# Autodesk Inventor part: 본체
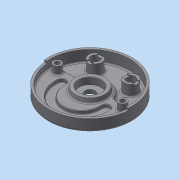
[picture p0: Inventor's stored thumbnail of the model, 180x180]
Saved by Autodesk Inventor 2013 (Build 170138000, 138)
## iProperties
Created: 2015-04
Part Number: 본체
Material: 일반
Document SubType Name: Modeling
Designer: Administrator
Density: 1 g/cm^3
Author: Administrator
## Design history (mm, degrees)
sketch "스케치1"
  geometry: C1 r 95 at (0, 0); 1 further point
  constraints: 1 centre point, 1 coincident
  dimensions: "d0" = 190 diameter of C1
extrude "돌출1" new body sketch "스케치1" distance "d1" = 32; taper "d2" = 0 deg
sketch "스케치2"
  geometry: L1 (-89.196, 12)-(-40.249, 12); L2 (40.249, 12)-(89.196, 12); C1 r 95 at (0, 0) reference; A1 r 90 centre (0, 0) between (89.196, 12) and (-89.196, 12); A2 r 42 centre (0, 0) between (40.249, 12) and (-40.249, 12)
  constraints: 4 end point, 4 point on circle, 2 centre point, 2 coincident, 2 horizontal
  dimensions: "d3" = 180 diameter of A1; "d4" = 84 diameter of A2; "d6" = 12 vertical distance of C1.centre L1.end; "d7" = 12 vertical distance of L2.end C1.centre
extrude "돌출2" cut sketch "스케치2" distance "d8" = 25; taper "d9" = 0 deg
fillet "모깎기1" dims "d10" = 10
sketch "스케치3"
  geometry: L1 (-47.117, 12)-(-76.916, 12) reference; L2 (76.916, 12)-(47.117, 12) reference; C1 r 95 at (0, 0) reference; C2 r 90 at (0, 0); A1 r 10 centre (-76.916, 22) between (-86.53, 24.75) and (-76.916, 12) reference; A2 r 90 centre (0, 0) between (86.53, 24.75) and (-86.53, 24.75) reference; A3 r 10 centre (76.916, 22) between (76.916, 12) and (86.53, 24.75) reference; A4 r 10 centre (47.117, 22) between (38.056, 17.769) and (47.117, 12) reference; A5 r 42 centre (0, 0) between (38.056, 17.769) and (-38.056, 17.769) reference; A6 r 10 centre (-47.117, 22) between (-47.117, 12) and (-38.056, 17.769) reference
  constraints: 1 centre point, 1 coincident
  dimensions: "d11" = 180 diameter of C2
extrude "돌출3" cut sketch "스케치3" distance "d12" = 18; taper "d13" = 0 deg
sketch "스케치6"
  geometry: C1 r 35 at (0, 0); A1 r 42 centre (0, 0) between (38.056, 17.769) and (-38.056, 17.769) reference
  constraints: 1 centre point, 1 coincident
  dimensions: "d34" = 70 diameter of C1
extrude "돌출4" join sketch "스케치6" distance "d35" = 10; taper "d36" = -10 deg
sketch "스케치7"
  geometry: C1 r 33.237 at (0, 0) reference; C2 r 25 at (0, 0)
  constraints: 1 centre point, 1 coincident
  dimensions: "d37" = 50 diameter of C2
extrude "돌출5" cut sketch "스케치7" distance "d38" = 15; taper "d39" = 0 deg
sketch "스케치8"
  geometry: C1 r 25 at (0, 0) reference; C2 r 11.5 at (0, 0)
  constraints: 1 centre point, 1 coincident
  dimensions: "d40" = 23 diameter of C2
extrude "돌출6" cut sketch "스케치8" stored distance "d41" = 15; taper "d42" = 0 deg
sketch "스케치9"
  geometry: C1 r 15 at (-40, 52); C2 r 15 at (40, 52); A1 r 90 centre (0, 0) between (86.53, 24.75) and (-86.53, 24.75) reference
  constraints: 2 centre point, 1 horizontal alignment
  dimensions: "d43" = 30 diameter of C1; "d44" = 30 diameter of C2; "d45" = 80 distance of C2.centre C1.centre; "d46" = 40 horizontal distance of C1.centre A1.centre; "d47" = 52 vertical distance of A1.centre C2.centre
extrude "돌출7" join sketch "스케치9" distance "d48" = 25; taper "d49" = 0 deg
sketch "스케치10"
  geometry: C1 r 15 at (0, 0) reference; C2 r 15 at (80, 0) reference; C3 r 10 at (0, 0); C4 r 10 at (80, 0); 1 further point
  constraints: 2 centre point, 2 coincident
  dimensions: "d50" = 20 diameter of C3; "d51" = 20 diameter of C4
extrude "돌출8" cut sketch "스케치10" stored distance "d52" = 25; taper "d53" = 0 deg
sketch "스케치11"
  geometry: C1 r 35 at (0, 0) reference; C2 r 9 at (-74, 0); C3 r 9 at (74, 0)
  constraints: 2 centre point, 2 horizontal alignment
  dimensions: "d54" = 18 diameter of C2; "d55" = 18 diameter of C3; "d56" = 148 distance of C3.centre C2.centre; "d57" = 74 distance of C2.centre C1.centre
extrude "돌출9" join sketch "스케치11" distance "d58" = 18; taper "d59" = 0 deg
sketch "스케치12"
  geometry: C1 r 9 at (-74, 0) reference; C2 r 10 at (40, 52) reference; C3 r 10 at (-40, 52) reference; C4 r 11.5 at (0, 0) reference; C5 r 95 at (0, 0) reference; C6 r 9 at (74, 0) reference; 2 further points
  constraints: 2 coincident
hole "구멍1" sketch "스케치12" at (-74, 0), (74, 0) diameter "d60" = 11; stored, may be unused: countersink angle "d64" = 90 deg, drill point angle "d66" = 0 deg; dims "d61" = 6, "d62" = 18, "d63" = 11, "d65" = 8
sketch "스케치13"
  geometry: L1 (-76.916, 12)-(-47.117, 12) reference; L2 (-59, -19)-(-41, -19); L3 (41, -19)-(59, -19); L4 (41, -19)-(41, -14); L5 (59, -19)-(59, -14); L6 (41, -14)-(59, -14); L7 (-59, -19)-(-59, -14); L8 (-41, -19)-(-41, -14); L9 (-41, -14)-(-59, -14); C1 r 35 at (0, 0) reference; A1 r 59 centre (0, -19) between (-59, -19) and (59, -19); A2 r 41 centre (0, -19) between (-41, -19) and (41, -19); A3 r 9 centre (50, -14) between (59, -14) and (41, -14); A4 r 9 centre (-50, -14) between (-41, -14) and (-59, -14)
  constraints: 16 end point, 8 point on circle, 4 centre point, 4 tangent, 2 midpoint, 2 parallel, 1 coincident, 1 collinear, 1 perpendicular, 1 vertical alignment
  dimensions: "d70" = 82 diameter of A2; "d72" = 19 distance of A1.centre C1.centre; "d75" = 5 distance of L4.end L3.start; "d76" = 5 distance of L5.end L3.end; "d79" = 59 radius of A1; "d80" = 5 distance of L7.end L2.start; "d81" = 5 distance of L8.end L2.end
extrude "돌출10" cut sketch "스케치13" distance "d83" = 7; taper "d84" = 0 deg
sketch "스케치16"
  geometry: L1 (0, 0)-(-112.328, 0); L2 (-89.658, -7.844)-(-94.638, -8.28); L3 (0, 0)-(105.461, 0); L4 (89.658, -7.844)-(94.638, -8.28); A1 r 95 centre (0, 0) between (-94.638, -8.28) and (94.638, -8.28) reference; A2 r 90 centre (0, 0) between (-89.658, -7.844) and (89.658, -7.844) reference
  constraints: 8 end point, 4 point on circle, 1 collinear, 1 horizontal
  dimensions: "d90" = 5 deg angle of L2 L1; "d91" = 5 deg angle of L4 L3; "d92" = 4.98097 horizontal distance of L2.start L2.end; "d93" = 4.98097 horizontal distance of L4.start L4.end
extrude "돌출12" cut sketch "스케치16" distance "d94" = 5; taper "d95" = 0 deg
fillet "모깎기2" dims "d96" = 0.3
fillet "모깎기3" dims "d97" = 5
chamfer "모따기1" distance "d99" = 1; stored, may be unused: second distance "d100" = 2, angle "d101" = 45 deg
fillet "모깎기5" dims "d102" = 1
fillet "모깎기6" dims "d103" = 3
chamfer "모따기2" distance "d104" = 1; stored, may be unused: second distance "d105" = 2, angle "d106" = 45 deg
sketch "스케치17"
  geometry: L1 (-6, 13.748)-(-6, 8); L2 (-6, -8)-(-6, -13.748); L3 (6, 13.748)-(6, 8); L4 (6, -8)-(6, -13.748); L5 (66.252, 6)-(72, 6); L6 (88, 6)-(93.748, 6); L7 (66.252, -6)-(72, -6); L8 (88, -6)-(93.748, -6); A1 r 10 centre (0, 0) between (-6, 8) and (-6, -8) reference; A2 r 15 centre (0, 0) between (-6, -13.748) and (6, -13.748) reference; A3 r 15 centre (80, 0) between (66.252, -6) and (66.252, 6) reference; A4 r 10 centre (80, 0) between (72, 6) and (88, 6) reference; 1 further point
  constraints: 16 end point, 16 point on circle, 12 parallel, 2 perpendicular, 2 vertical, 1 horizontal alignment, 1 vertical alignment
  dimensions: "d110" = 12 distance of L7.start L5.start; "d112" = 12 distance of L3.start L1.start
extrude "돌출13" cut sketch "스케치17" distance "d113" = 3; taper "d114" = 0 deg
fillet "모깎기7" dims "d115" = 3
node "솔리드1"
node "투영된 루프1"
node "투영된 루프2"
other parameters: "d5" = 12, "d17" = 19, "d107" = 12
